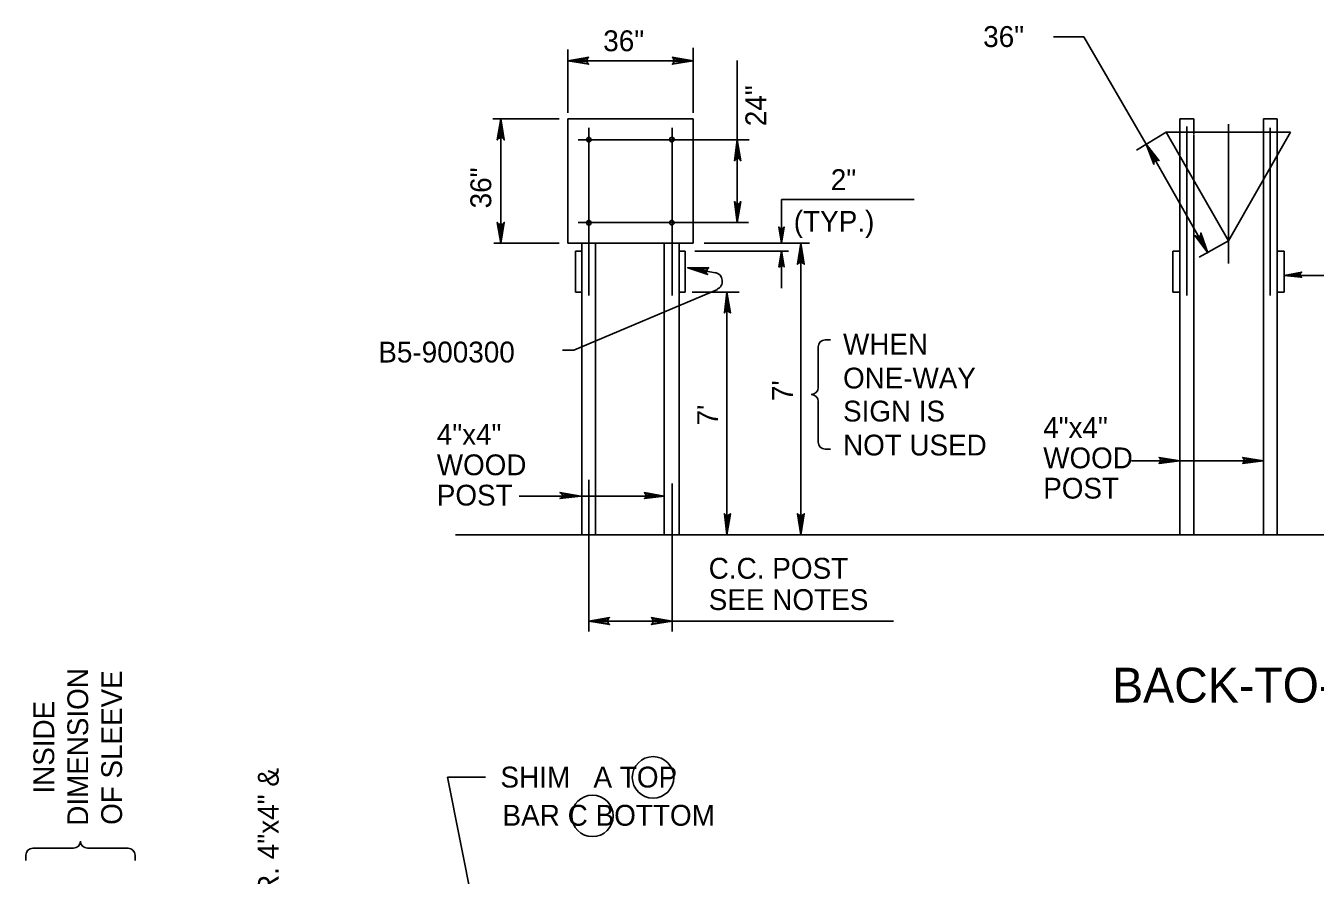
# Model space of a CAD drawing. Extents: x 648590 to 650336, y 294467 to 295061.
# Drawn here: x 648813.8 to 648999.2, y 294632.9 to 294755 of the extents above; entities that cross this region are included whole.
import ezdxf

# ---------------------------------------------------------------- set-up
doc = ezdxf.new("R2010")
doc.units = 0
doc.layers.add('2', color=7, linetype='Continuous')
doc.layers.add('3', color=7, linetype='Continuous')

msp = doc.modelspace()

# ---------------------------------------------------------------- linework, layer by layer
at = {"layer": '2'}
for p, q in [((648961.6, 294753.43), (648965.97, 294753.43)), ((648965.97, 294753.43), (648974.9, 294737.97)), ((648891.77, 294742.49), (648891.77, 294751.61)), ((648909.77, 294742.49), (648909.77, 294751.86)), ((648891.77, 294749.99), (648909.77, 294749.99)), ((648916.12, 294726.74), (648916.12, 294750.02)), ((648890.52, 294741.61), (648881.01, 294741.61)), ((648882.13, 294723.74), (648882.13, 294741.61)), ((648891.77, 294723.74), (648891.77, 294741.61)), ((648909.77, 294741.61), (648891.77, 294741.61)), ((648894.77, 294716.24), (648894.77, 294740.36)), ((648906.77, 294716.24), (648906.77, 294740.36)), ((648909.77, 294723.74), (648909.77, 294741.61)), ((648981.77, 294741.61), (648979.77, 294741.61)), ((648979.77, 294739.36), (648979.77, 294741.61)), ((648980.77, 294716.24), (648980.77, 294740.52)), ((648981.77, 294739.49), (648981.77, 294741.61)), ((648986.77, 294720.86), (648986.77, 294740.86)), ((648993.77, 294741.61), (648991.77, 294741.61)), ((648991.77, 294739.24), (648991.77, 294741.61)), ((648992.75, 294716.24), (648992.75, 294740.36)), ((648993.77, 294739.36), (648993.77, 294741.61)), ((648893.27, 294738.61), (648908.27, 294738.61)), ((648894.77, 294738.61), (648894.77, 294738.61)), ((648906.77, 294738.61), (648906.77, 294738.61)), ((648908.27, 294738.61), (648917.86, 294738.61)), ((648977.77, 294739.74), (648973.52, 294737.11)), ((648986.77, 294724.11), (648977.77, 294739.74)), ((648995.64, 294739.74), (648977.77, 294739.74)), ((648977.77, 294739.74), (648992.64, 294739.74)), ((648979.77, 294736.26), (648979.77, 294739.36)), ((648981.77, 294732.79), (648981.77, 294739.36)), ((648995.64, 294739.74), (648986.77, 294724.11)), ((648991.77, 294732.91), (648991.77, 294739.24)), ((648993.77, 294736.44), (648993.77, 294739.36)), ((648974.89, 294737.99), (648983.77, 294722.36)), ((648993.77, 294681.86), (648993.77, 294736.44)), ((648979.77, 294681.86), (648979.77, 294736.26)), ((648981.77, 294681.86), (648981.77, 294732.79)), ((648991.77, 294681.86), (648991.77, 294732.91)), ((648922.49, 294723.74), (648922.49, 294730.02)), ((648922.49, 294730.02), (648941.54, 294730.02)), ((648893.27, 294726.74), (648908.27, 294726.74)), ((648894.77, 294726.74), (648894.77, 294726.74)), ((648906.77, 294726.74), (648906.77, 294726.74)), ((648908.27, 294726.74), (648917.75, 294726.74)), ((648890.52, 294723.74), (648881.13, 294723.74)), ((648909.77, 294723.74), (648891.77, 294723.74)), ((648893.77, 294681.86), (648893.77, 294723.74)), ((648895.77, 294681.86), (648895.77, 294723.74)), ((648905.64, 294681.86), (648905.64, 294723.74)), ((648907.77, 294681.86), (648907.77, 294723.74)), ((648911.39, 294723.74), (648926.52, 294723.74)), ((648925.27, 294681.86), (648925.27, 294723.74)), ((648986.77, 294724.11), (648982.52, 294721.74)), ((648892.89, 294716.74), (648892.89, 294722.61)), ((648892.89, 294722.61), (648893.77, 294722.61)), ((648907.77, 294722.61), (648908.64, 294722.61)), ((648908.64, 294716.74), (648908.64, 294722.61)), ((648910.02, 294722.61), (648923.49, 294722.61)), ((648922.49, 294717.28), (648922.49, 294722.61)), ((648978.77, 294716.74), (648978.77, 294722.61)), ((648978.77, 294722.61), (648979.77, 294722.61)), ((648993.77, 294722.61), (648994.77, 294722.61)), ((648994.77, 294716.74), (648994.77, 294722.61)), ((648909.02, 294720.24), (648913.02, 294719.49)), ((648994.77, 294719.11), (649042.14, 294719.11)), ((648892.64, 294708.36), (648913.27, 294717.11)), ((648892.89, 294716.74), (648893.77, 294716.74)), ((648907.77, 294716.74), (648908.64, 294716.74)), ((648909.64, 294716.74), (648916.39, 294716.74)), ((648914.64, 294681.86), (648914.64, 294716.74)), ((648978.77, 294716.74), (648979.77, 294716.74)), ((648993.77, 294716.74), (648994.77, 294716.74)), ((648891.02, 294708.36), (648892.64, 294708.36)), ((648991.77, 294692.47), (648972.81, 294692.47)), ((648894.77, 294667.95), (648894.77, 294689.74)), ((648906.77, 294667.95), (648906.77, 294689.24)), ((648905.64, 294687.42), (648884.77, 294687.42)), ((648875.64, 294681.86), (649127.52, 294681.86)), ((648894.77, 294669.45), (648938.6, 294669.45))]:
    msp.add_line(p, q, dxfattribs=at)
for points in [[(648894.64, 294749.61), (648894.52, 294749.86), (648891.77, 294749.99), (648894.64, 294749.61), (648894.77, 294749.49), (648891.77, 294749.99), (648894.52, 294750.11), (648894.64, 294750.36), (648891.77, 294749.99), (648894.77, 294750.49), (648894.64, 294750.36)], [(648906.89, 294750.36), (648907.02, 294750.11), (648909.77, 294749.99), (648906.89, 294750.36), (648906.77, 294750.49), (648909.77, 294749.99), (648907.02, 294749.86), (648906.89, 294749.61), (648909.77, 294749.99), (648906.77, 294749.49), (648906.89, 294749.61)], [(648882.51, 294738.86), (648882.38, 294738.86), (648882.13, 294741.61), (648882.51, 294738.86), (648882.63, 294738.61), (648882.13, 294741.61), (648882.01, 294738.86), (648881.76, 294738.86), (648882.13, 294741.61), (648881.63, 294738.61), (648881.76, 294738.86)], [(648915.87, 294735.86), (648916, 294735.86), (648916.12, 294738.61), (648915.87, 294735.86), (648915.75, 294735.61), (648916.12, 294738.61), (648916.25, 294735.99), (648916.5, 294735.86), (648916.12, 294738.61), (648916.62, 294735.61), (648916.5, 294735.86)], [(648976.02, 294735.36), (648976.14, 294735.49), (648974.89, 294737.99), (648976.02, 294735.36), (648976.02, 294735.11), (648974.89, 294737.99), (648976.39, 294735.61), (648976.64, 294735.74), (648974.89, 294737.99), (648976.77, 294735.61), (648976.64, 294735.74)], [(648916.5, 294729.49), (648916.25, 294729.36), (648916.12, 294726.74), (648916.5, 294729.49), (648916.62, 294729.74), (648916.12, 294726.74), (648916, 294729.36), (648915.87, 294729.49), (648916.12, 294726.74), (648915.75, 294729.74), (648915.87, 294729.49)], [(648881.76, 294726.49), (648882.01, 294726.49), (648882.13, 294723.74), (648881.76, 294726.49), (648881.63, 294726.74), (648882.13, 294723.74), (648882.26, 294726.49), (648882.51, 294726.49), (648882.13, 294723.74), (648882.63, 294726.74), (648882.51, 294726.49)], [(648922.74, 294725.99), (648922.61, 294725.86), (648922.49, 294723.74), (648922.74, 294725.99), (648922.86, 294726.11), (648922.49, 294723.74), (648922.36, 294725.86), (648922.24, 294725.99), (648922.49, 294723.74), (648922.11, 294726.11), (648922.24, 294725.99)], [(648982.77, 294724.99), (648982.64, 294724.86), (648983.77, 294722.36), (648982.77, 294724.99), (648982.77, 294725.24), (648983.77, 294722.36), (648982.39, 294724.74), (648982.14, 294724.74), (648983.77, 294722.36), (648981.89, 294724.86), (648982.14, 294724.74)], [(648924.89, 294720.86), (648925.14, 294720.99), (648925.27, 294723.74), (648924.89, 294720.86), (648924.77, 294720.74), (648925.27, 294723.74), (648925.39, 294720.99), (648925.64, 294720.86), (648925.27, 294723.74), (648925.77, 294720.74), (648925.64, 294720.86)], [(648922.24, 294720.36), (648922.36, 294720.49), (648922.49, 294722.61), (648922.24, 294720.36), (648922.11, 294720.36), (648922.49, 294722.61), (648922.61, 294720.49), (648922.74, 294720.49), (648922.49, 294722.61), (648922.86, 294720.36), (648922.74, 294720.49)], [(648911.77, 294719.36), (648911.64, 294719.61), (648909.02, 294720.24), (648911.77, 294719.36), (648911.89, 294719.24), (648909.02, 294720.24), (648911.77, 294719.86), (648911.89, 294720.11), (648909.02, 294720.24), (648912.02, 294720.24), (648911.89, 294720.11)], [(648997.14, 294718.86), (648997.02, 294718.99), (648994.77, 294719.11), (648997.14, 294718.86), (648997.27, 294718.86), (648994.77, 294719.11), (648997.02, 294719.24), (648997.14, 294719.49), (648994.77, 294719.11), (648997.27, 294719.61), (648997.14, 294719.49)], [(648914.39, 294713.86), (648914.52, 294713.99), (648914.64, 294716.74), (648914.39, 294713.86), (648914.27, 294713.74), (648914.64, 294716.74), (648914.77, 294713.99), (648915.02, 294713.86), (648914.64, 294716.74), (648915.14, 294713.74), (648915.02, 294713.86)], [(648976.89, 294692.85), (648977.02, 294692.6), (648979.77, 294692.47), (648976.89, 294692.85), (648976.77, 294692.97), (648979.77, 294692.47), (648977.02, 294692.47), (648976.89, 294692.22), (648979.77, 294692.47), (648976.77, 294692.1), (648976.89, 294692.22)], [(648988.89, 294692.85), (648989.02, 294692.6), (648991.77, 294692.47), (648988.89, 294692.85), (648988.77, 294692.97), (648991.77, 294692.47), (648989.02, 294692.47), (648988.89, 294692.22), (648991.77, 294692.47), (648988.77, 294692.1), (648988.89, 294692.22)], [(648890.89, 294687.79), (648891.02, 294687.54), (648893.64, 294687.42), (648890.89, 294687.79), (648890.64, 294687.92), (648893.64, 294687.42), (648891.02, 294687.42), (648890.89, 294687.17), (648893.64, 294687.42), (648890.64, 294687.04), (648890.89, 294687.17)], [(648902.89, 294687.79), (648903.02, 294687.54), (648905.64, 294687.42), (648902.89, 294687.79), (648902.77, 294687.92), (648905.64, 294687.42), (648903.02, 294687.42), (648902.89, 294687.17), (648905.64, 294687.42), (648902.77, 294687.04), (648902.89, 294687.17)], [(648915.02, 294684.74), (648914.77, 294684.61), (648914.64, 294681.86), (648915.02, 294684.74), (648915.14, 294684.86), (648914.64, 294681.86), (648914.52, 294684.61), (648914.39, 294684.74), (648914.64, 294681.86), (648914.27, 294684.86), (648914.39, 294684.74)], [(648925.64, 294684.74), (648925.39, 294684.61), (648925.27, 294681.86), (648925.64, 294684.74), (648925.77, 294684.86), (648925.27, 294681.86), (648925.14, 294684.61), (648924.89, 294684.74), (648925.27, 294681.86), (648924.77, 294684.86), (648924.89, 294684.74)], [(648897.64, 294669.07), (648897.52, 294669.32), (648894.77, 294669.45), (648897.64, 294669.07), (648897.77, 294668.95), (648894.77, 294669.45), (648897.52, 294669.57), (648897.64, 294669.82), (648894.77, 294669.45), (648897.77, 294669.95), (648897.64, 294669.82)], [(648903.89, 294669.82), (648904.02, 294669.57), (648906.77, 294669.45), (648903.89, 294669.82), (648903.77, 294669.95), (648906.77, 294669.45), (648904.02, 294669.32), (648903.89, 294669.07), (648906.77, 294669.45), (648903.77, 294668.95), (648903.89, 294669.07)]]:
    msp.add_lwpolyline(points, dxfattribs=at)
for centre in [(648894.79, 294738.64), (648906.74, 294738.65), (648906.74, 294726.71), (648894.79, 294726.7)]:
    msp.add_circle(centre, 0.331, dxfattribs=at)
at = {"layer": '3'}
for p, q in [((648927.77, 294708.85), (648927.77, 294703.02)), ((648929.53, 294709.86), (648928.78, 294709.86)), ((648927.77, 294701), (648927.77, 294695.17)), ((648928.78, 294694.16), (648929.53, 294694.16)), ((648879.95, 294647.03), (648874.45, 294647.03)), ((648874.45, 294647.03), (648881.83, 294610.28)), ((648820.69, 294636.81), (648814.86, 294636.81)), ((648828.54, 294636.81), (648822.71, 294636.81)), ((648813.84, 294635.8), (648813.84, 294635.05)), ((648829.55, 294635.05), (648829.55, 294635.8))]:
    msp.add_line(p, q, dxfattribs=at)
for centre in [(648904.02, 294646.98), (648895.31, 294641.44)]:
    msp.add_circle(centre, 2.98, dxfattribs=at)
for centre, radius, start, end in [((648912.73, 294718.3), 1.25, 293.1857, 78.8253), ((648928.78, 294708.85), 1.01, 90, 180), ((648926.76, 294703.02), 1.01, 270, 360), ((648926.76, 294701), 1.01, 360, 90), ((648928.78, 294695.17), 1.01, 180, 270), ((648814.86, 294635.8), 1.01, 90, 180), ((648820.69, 294637.82), 1.01, 270, 360), ((648822.71, 294637.82), 1.01, 180, 270), ((648828.54, 294635.8), 1.01, 360, 90)]:
    msp.add_arc(centre, radius, start, end, dxfattribs=at)

# ---------------------------------------------------------------- texts
at = {"layer": '2'}
for s, p in [('DIMENSION', (648822.81, 294640.03)), ('OF SLEEVE', (648827.68, 294640.16)), ('INSIDE', (648817.93, 294644.66))]:
    msp.add_text(s, height=2.988, rotation=90, dxfattribs=at).set_placement(p)
for s, height, p in [('BACK-TO-BACK MOUNTS', 5, (648970.02, 294657.74)), ('SHIM   A TOP', 3, (648882.08, 294645.52))]:
    msp.add_text(s, height=height, dxfattribs=at).set_placement(p)
at = {"layer": '3'}
for s, height, p in [('36"', 3, (648951.48, 294751.96)), ('36"', 3, (648896.86, 294751.35)), ('2"', 3, (648929.57, 294731.39)), ('(TYP.)', 3, (648924.25, 294725.4)), ('WHEN', 2.988, (648931.34, 294707.75)), ('B5-900300', 3, (648864.52, 294706.61)), ('ONE-WAY', 2.988, (648931.34, 294702.88)), ('SIGN IS', 2.988, (648931.34, 294698.13)), ('4"x4"', 2.988, (648872.94, 294694.78)), ('4"x4"', 2.988, (648960.12, 294695.77)), ('NOT USED', 2.988, (648931.34, 294693.25)), ('WOOD', 2.988, (648960.12, 294691.41)), ('WOOD', 2.988, (648872.94, 294690.41)), ('POST', 2.988, (648960.12, 294687.05)), ('POST', 2.988, (648872.94, 294686.05)), ('C.C. POST', 3, (648912.02, 294675.53)), ('SEE NOTES', 3, (648912.02, 294671.03)), ('BAR C BOTTOM', 3, (648882.38, 294640.03))]:
    msp.add_text(s, height=height, dxfattribs=at).set_placement(p)
for s, p in [('24"', (648920.3, 294740.57)), ('36"', (648880.76, 294728.76)), ("7'", (648924.13, 294701.06)), ("7'", (648913.37, 294697.56)), (' 1/8" CLR. 4"x4" &', (648850.2, 294615.73))]:
    msp.add_text(s, height=3, rotation=90, dxfattribs=at).set_placement(p)

doc.saveas('drawing.dxf')
